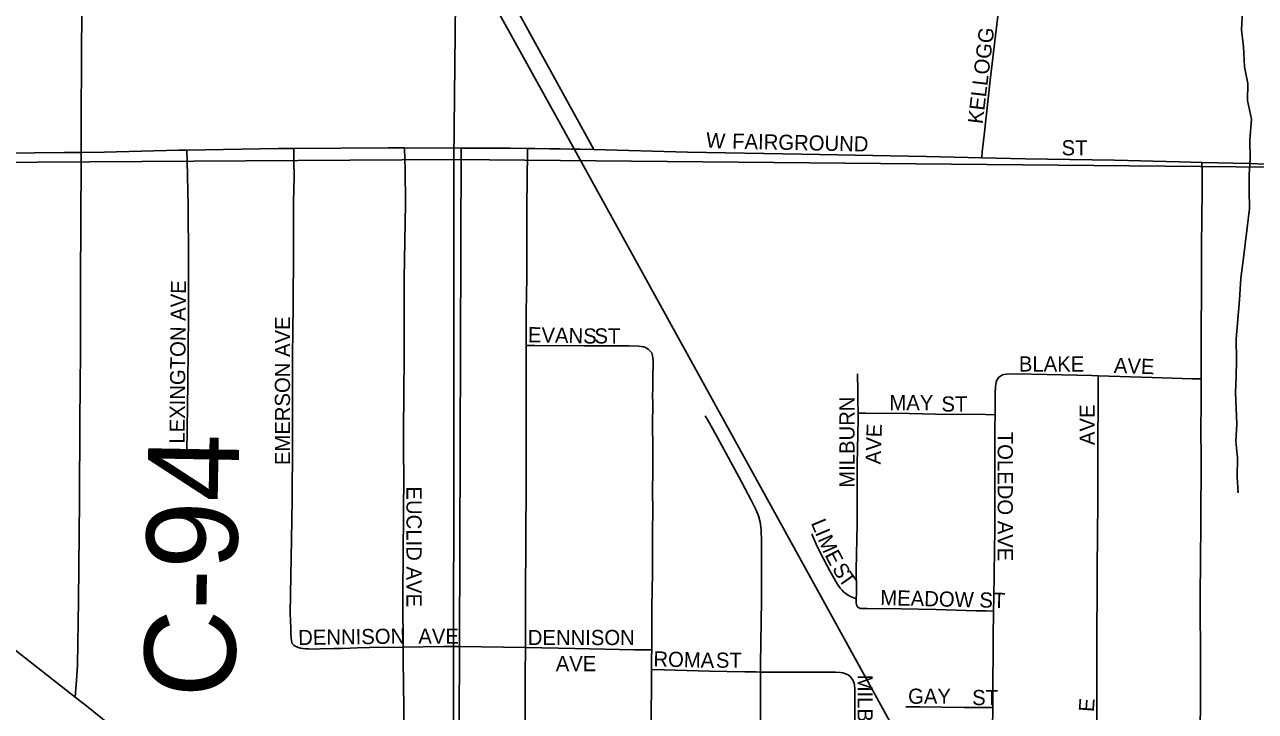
# Model space of a CAD drawing. Extents: x 1584893 to 1934202, y 663575 to 1091909.
# Drawn here: x 1786466 to 1790524, y 945999 to 948263 of the extents above; entities that cross this region are included whole.
import ezdxf

# ---------------------------------------------------------------- set-up
doc = ezdxf.new("R2010")
doc.units = 0
for name, color, linetype in [('GM_X_City_Street', 7, 'Continuous'), ('GM_X_City_Street_Text', 7, 'Continuous'), ('GM_X_Corporation', 7, 'Continuous'), ('GM_X_County_Road', 7, 'Continuous'), ('GM_X_County_Road_Text', 7, 'Continuous'), ('GM_X_Minor_River', 7, 'Continuous'), ('GM_X_Rail_Line', 7, 'Continuous'), ('GM_X_Section', 7, 'Continuous'), ('GM_X_State_Route', 7, 'Continuous'), ('GM_X_Township_Subdivision', 7, 'Continuous'), ('GM_X_Township_Subdivision_Text', 7, 'Continuous')]:
    doc.layers.add(name, color=color, linetype=linetype)

msp = doc.modelspace()

# ---------------------------------------------------------------- linework, layer by layer
at = {"layer": 'GM_X_City_Street'}
for points in [[(1789621.1, 947824.3), (1789623.2, 947844.1), (1789628.9, 947898.8), (1789648.8, 948079.7), (1789674.4, 948291.5)], [(1788119.7, 947205.2), (1788119.7, 947314.6), (1788121.2, 947429.3), (1788121.7, 947642.4), (1788122.3, 947773.6), (1788123.2, 947822.8), (1788123.9, 947855.2)], [(1788342.3, 947851), (1788651.7, 947843.1), (1789028.3, 947835.8), (1789437.6, 947828.2), (1789621.1, 947824.3)], [(1789621.1, 947824.3), (1789765, 947821.1), (1790059.6, 947815.7), (1790272.5, 947811), (1790347.4, 947809)], [(1790344.6, 947094.7), (1790344.6, 947271.2), (1790345.5, 947369.4), (1790345.9, 947533.2), (1790348, 947713.5), (1790347.6, 947784.3), (1790347.4, 947809)], [(1790347.4, 947809), (1790501.7, 947804.7), (1790559.1, 947802.8)], [(1788116.7, 946209.3), (1788116.7, 946217.2), (1788116.7, 946396.9), (1788118.4, 946544.5), (1788119, 946773.5), (1788119.7, 947167), (1788119.7, 947205.2)], [(1788119.7, 947205.2), (1788147.5, 947205), (1788311.2, 947203.9), (1788458.6, 947204.1), (1788491.2, 947202.5), (1788498.4, 947202), (1788507.2, 947200.4), (1788512.7, 947198.2), (1788516.2, 947196.1), (1788521.8, 947192.6), (1788528.6, 947186.7)], [(1788533.2, 946201.4), (1788534.1, 946242.1), (1788533.4, 946340.6), (1788536, 946455.6), (1788535.5, 946487.9), (1788535.4, 946504.2), (1788535.7, 946602.3), (1788536.4, 946651.3), (1788536, 946733.4), (1788536.6, 946782.6), (1788537.2, 946864.6), (1788535.6, 946946.4), (1788536.6, 947011.3), (1788536.2, 947043.9), (1788536.6, 947059.3), (1788536.8, 947075.2), (1788536.7, 947090.8), (1788537.5, 947155.9), (1788537.3, 947163.6), (1788536.1, 947172.3), (1788533.2, 947180.4), (1788528.6, 947186.7)], [(1789213.6, 946981.5), (1789213.1, 947023.3), (1789212.5, 947066), (1789212, 947101), (1789211.9, 947111.3)], [(1789671.1, 947091.3), (1789677.8, 947100.3), (1789683.2, 947104.5), (1789689.4, 947108.1), (1789695.7, 947109.6), (1789703.3, 947110.3), (1789736.2, 947111.7), (1789835.5, 947109.3), (1789984.5, 947105.8), (1790005, 947105.2)], [(1789995.8, 945159.5), (1789995.8, 945195.4), (1789995.8, 945385.1), (1789996.3, 945482.8), (1789997.2, 945677.2), (1789998, 945820.7), (1790000.3, 945980.3), (1790001.3, 946163.8), (1790001.9, 946488.6), (1790003.1, 946563.6), (1790004.1, 946705.9), (1790004.3, 946835.3), (1790004.9, 947065.2), (1790004.9, 947081.6), (1790005, 947105.2)], [(1790005, 947105.2), (1790183.1, 947100), (1790315.4, 947095.6), (1790344.6, 947094.7)], [(1790336.9, 945152.3), (1790337.4, 945195.9), (1790339.7, 945425.5), (1790340.1, 945605.5), (1790340.1, 945687.6), (1790338.9, 945721), (1790339.2, 945734.4), (1790339.5, 945781.5), (1790339.8, 945847.1), (1790342.5, 946010.9), (1790342.5, 946125.8), (1790341.8, 946404.4), (1790342.2, 946469.8), (1790344.9, 946814.2), (1790344.2, 946945.5), (1790344.6, 946994.5), (1790344.6, 947094.7)], [(1789665.2, 946977), (1789665.4, 947035.7), (1789666.1, 947055), (1789666.4, 947062.4), (1789667.2, 947068.6), (1789668, 947077.2), (1789669.2, 947083.1), (1789671.1, 947091.3)], [(1788892, 946128.3), (1788892.2, 946153), (1788894.8, 946365.5), (1788895.1, 946463.2), (1788894.9, 946560.7), (1788895.1, 946570.8), (1788894.5, 946583.8), (1788893.8, 946593.8), (1788892.6, 946607.5), (1788890.7, 946623), (1788885.7, 946643.5), (1788877.1, 946662.1), (1788867.9, 946681.8), (1788860.9, 946695.1), (1788851.2, 946713.5), (1788820.3, 946771.8), (1788758, 946887.2), (1788718.1, 946958.8), (1788709.9, 946973)], [(1789207.3, 946369.5), (1789207.6, 946376.7), (1789207.9, 946383.2), (1789208.4, 946400.6), (1789207.8, 946466.8), (1789211.1, 946615.5), (1789211, 946813.9), (1789213.9, 946962.5), (1789213.6, 946981.5)], [(1789213.6, 946981.5), (1789239.5, 946981.5), (1789272.3, 946981.4), (1789337.9, 946981.5), (1789469.1, 946979.1), (1789633.2, 946977.3), (1789665.2, 946977)], [(1789660.2, 946329.5), (1789660.9, 946373.3), (1789662.3, 946454.7), (1789664.1, 946600.8), (1789664.5, 946693.9), (1789665, 946937.4), (1789665.2, 946977)], [(1789207.3, 946369.5), (1789191.2, 946376), (1789178.6, 946382.8), (1789165.7, 946393.1), (1789160.8, 946398), (1789154.7, 946405.4), (1789145.1, 946418.8), (1789120.7, 946462), (1789090.2, 946520.8), (1789074.9, 946550.2), (1789068.3, 946565.3), (1789062.7, 946580.9), (1789062, 946583.6)], [(1789215.8, 946340.2), (1789211.6, 946343.5), (1789208.7, 946349.7), (1789207.7, 946356.5), (1789207.3, 946369.5)], [(1789215.8, 946340.2), (1789218.9, 946338.9), (1789221.6, 946338.3), (1789225, 946337.9), (1789228.7, 946338.1), (1789234.1, 946338.1), (1789243.2, 946338.2), (1789355.4, 946337.3), (1789470.9, 946335.1), (1789602.8, 946330.4), (1789635.7, 946329.9), (1789660.2, 946329.5)], [(1789657.9, 946011.8), (1789658.3, 946046.6), (1789658.9, 946242.8), (1789660.2, 946329.5)], [(1788116.7, 946209.3), (1787899.9, 946213.1)], [(1788112.7, 945197), (1788112.9, 945238.3), (1788113.4, 945402.2), (1788115.8, 945582.3), (1788115.4, 945664.2), (1788114, 945827.5), (1788114.5, 945876.3), (1788115.8, 945957.5), (1788116.3, 946119.6), (1788116.7, 946209.3)], [(1788116.7, 946209.3), (1788279.4, 946206.4), (1788475.9, 946201.9), (1788508.6, 946201.6), (1788533.2, 946201.4)], [(1788532.7, 946136.7), (1788532.6, 946176.4), (1788533.2, 946201.4)], [(1788527.7, 945188.6), (1788528.4, 945224), (1788529.2, 945256.8), (1788528.1, 945388.2), (1788530.9, 945568.8), (1788530.6, 945683.7), (1788532.1, 945880.8), (1788531.5, 945946.5), (1788532.8, 946127.1), (1788532.7, 946136.7)], [(1788532.7, 946136.7), (1788574.7, 946135.6), (1788724.1, 946131.5), (1788840.3, 946128.7), (1788876.9, 946128.7), (1788892, 946128.3)], [(1788886.3, 945181), (1788886.5, 945221.2), (1788888.9, 945646.2), (1788889.4, 945891.6), (1788891.4, 945973.4), (1788892.1, 946087.7), (1788892, 946128.3)], [(1788892, 946128.3), (1789039.5, 946128.4), (1789139, 946127.5), (1789155.6, 946126.5), (1789163.6, 946125.4), (1789171.8, 946122.7), (1789180.4, 946119)], [(1789199.8, 945543.2), (1789199.9, 945549.9), (1789201.6, 945664.2), (1789202.8, 945713.1), (1789201.9, 945748.6), (1789201.2, 945778.5), (1789203, 945942.5), (1789202.8, 946024.6), (1789202.6, 946073.9), (1789202.4, 946077.5), (1789202, 946081.5), (1789201.3, 946085.9), (1789200.2, 946090.1), (1789198.3, 946096.9), (1789196.8, 946101.1), (1789194.3, 946105), (1789191.1, 946109.8), (1789187.1, 946114), (1789180.4, 946119)], [(1789370.7, 946013.8), (1789418.1, 946013.9), (1789562.4, 946011.7), (1789625.9, 946011.8), (1789657.9, 946011.8)], [(1789863.6, 945162), (1789844.5, 945195), (1789819.9, 945237.6), (1789740.4, 945380.5), (1789677, 945495.1), (1789663, 945525.3), (1789657.8, 945541.4), (1789655.1, 945558), (1789653.7, 945591.2), (1789653.1, 945656.5), (1789653.5, 945721.4), (1789656, 945867.5), (1789657.9, 946011.8)]]:
    msp.add_lwpolyline(points, dxfattribs=at)
at = {"layer": 'GM_X_Corporation'}
msp.add_lwpolyline([(1787866.1, 943680.2), (1787892.4, 945033.6), (1787894.8, 945201.7), (1787899.9, 946213.1), (1787904.8, 947855.9), (1788123.9, 947855.1), (1788342.3, 947851), (1786892.8, 950488)], dxfattribs=at)
at = {"layer": 'GM_X_County_Road'}
for points in [[(1786651.8, 947841.9), (1786651.8, 947982.3), (1786652.7, 948122.4), (1786654.3, 948351.1), (1786653.5, 948531.5)], [(1786301.9, 947838), (1786596.2, 947841.1), (1786651.8, 947841.9)], [(1786632, 946045.6), (1786636.2, 946102.1), (1786639.7, 946151), (1786643.2, 946364.2), (1786646.5, 946692.7), (1786647.8, 946955.4), (1786650.1, 947185.3), (1786650.1, 947415.1), (1786651.8, 947813.8), (1786651.8, 947841.9)], [(1786651.8, 947841.9), (1786727.4, 947842.7), (1786973.6, 947849.1), (1787000.9, 947849.4)], [(1787000.9, 947849.4), (1787121.1, 947851.2), (1787301.6, 947854.6), (1787352.8, 947854.9)], [(1787352.8, 947854.9), (1787662.9, 947856.7), (1787717.9, 947856.5)], [(1787717.9, 947856.5), (1787904.8, 947855.9)], [(1787904.8, 947855.9), (1788066.3, 947855.7), (1788123.9, 947855.2)], [(1788123.9, 947855.2), (1788148.8, 947854.9), (1788231.3, 947853.6), (1788297.3, 947852), (1788342.3, 947851)]]:
    msp.add_lwpolyline(points, dxfattribs=at)
at = {"layer": 'GM_X_Minor_River'}
msp.add_lwpolyline([(1790480.6, 948308), (1790477.6, 948246), (1790484.7, 948189.8), (1790487.5, 948123.7), (1790498.6, 948069.4), (1790497.7, 948013.4), (1790510.6, 947951.2), (1790505.5, 947883.2), (1790506.5, 947821.1), (1790503.6, 947769.1), (1790502.8, 947717.1), (1790503.8, 947657), (1790496.7, 947593.1), (1790482.9, 947485.3), (1790476, 947427.3), (1790470.8, 947355.4), (1790460.7, 947227.4), (1790461.5, 947155.4), (1790460.6, 947103.3), (1790457.7, 947049.3), (1790462, 946945.2), (1790459.1, 946889.2), (1790464.2, 946835.1), (1790463.1, 946771), (1790466.3, 946720.9), (1790464.3, 946725)], dxfattribs=at)
at = {"layer": 'GM_X_Rail_Line'}
msp.add_lwpolyline([(1789400.6, 945815.7), (1789127.2, 946312.4), (1788279, 947851.2), (1787937.1, 948469), (1787819.8, 948676.5), (1787624.4, 949012.2), (1787505.6, 949248.9), (1787424.3, 949403.4), (1787265.8, 949688.4), (1785374.8, 953122.4), (1784266.3, 955133.8), (1784098.1, 955439.7), (1784015.4, 955585.7), (1783944.2, 955691.7), (1783794.4, 955967.2), (1783640.1, 956257.8), (1783519.3, 956485.2)], dxfattribs=at)
at = {"layer": 'GM_X_Section'}
for points in [[(1782828, 953093.9), (1787937.3, 953135.4), (1787881.1, 947818.8), (1782733.9, 947785.7)], [(1787937.3, 953135.4), (1793211.7, 953051.5), (1793155.7, 947768.8), (1787881.1, 947818.8)], [(1782733.9, 947785.7), (1787881.1, 947818.8), (1787878.9, 942509.8), (1782631.8, 942485.5)], [(1787881.1, 947818.8), (1793155.7, 947768.8), (1793145.7, 942483.9), (1787878.9, 942509.8)]]:
    msp.add_lwpolyline(points, close=True, dxfattribs=at)
at = {"layer": 'GM_X_State_Route'}
msp.add_lwpolyline([(1784411.4, 947809), (1784778, 947519.7), (1784956.6, 947377.5), (1785123.6, 947244.7), (1785149.2, 947224.2), (1785341.7, 947070.9), (1785637.5, 946836.6), (1785996.9, 946550.6), (1786138.3, 946438.4), (1786290.4, 946316.4), (1786407, 946222.8), (1786632, 946045.6), (1786664.7, 946019.9), (1787048.2, 945711.3), (1787418.9, 945413.2), (1787632.7, 945242.8), (1787680.6, 945204.5), (1787741.5, 945155.3), (1787772.6, 945130), (1787892.5, 945033.6)], dxfattribs=at)
at = {"layer": 'GM_X_Township_Subdivision'}
for points in [[(1787000, 946850.3), (1787001.4, 946931.9), (1787004.1, 947078.7), (1787005.9, 947307), (1787006.2, 947421.2), (1787005.7, 947486.4), (1787004.6, 947665.8), (1787001.6, 947812.5), (1787000.9, 947849.4)], [(1787347.3, 946222.5), (1787345.2, 946231.8), (1787344.1, 946240.4), (1787342.9, 946257), (1787342.8, 946272.6), (1787341.3, 946321.1), (1787342.1, 946385), (1787345.2, 946565.2), (1787347.2, 946696.7), (1787348.5, 946877.2), (1787348.3, 946973.5), (1787348.8, 947057.1), (1787349, 947172.1), (1787351, 947336.3), (1787351.7, 947516.8), (1787352.6, 947680.8), (1787353.6, 947718.6), (1787353.9, 947762.8), (1787353.3, 947812), (1787352.8, 947854.9)], [(1787713.8, 946210.9), (1787712.8, 946362.7), (1787713.9, 946542.8), (1787714.8, 946624.7), (1787714.8, 946640.9), (1787715.5, 946787.9), (1787715, 946837), (1787715, 946918.9), (1787715.4, 947049.9), (1787716.9, 947164.6), (1787716.7, 947426.7), (1787721, 947672.3), (1787719.9, 947786.9), (1787719, 947819.6), (1787717.9, 947856.5)], [(1787713.8, 946210.9), (1787602.6, 946209.4), (1787563, 946208), (1787539.5, 946207.4), (1787509.9, 946206.5), (1787485.1, 946205.8), (1787440.1, 946204.5), (1787423.6, 946203.9), (1787402.4, 946204.4), (1787391.3, 946205.1), (1787383.2, 946205.8), (1787375.2, 946207.3), (1787367.4, 946209.5), (1787362.7, 946211.7), (1787357.8, 946213.9), (1787353.7, 946217.1), (1787347.3, 946222.5)], [(1787899.9, 946213.1), (1787846.8, 946212.8), (1787713.8, 946210.9)], [(1787717.9, 945853.8), (1787714.1, 946166.2), (1787713.8, 946210.9)]]:
    msp.add_lwpolyline(points, dxfattribs=at)

# ---------------------------------------------------------------- texts
at = {"layer": 'GM_X_City_Street_Text'}
for s, rotation, p in [('KELLOGG', 83.0895, (1789624.4, 947933.8)), ('W', 355.6039, (1788710.4, 947858.5)), ('FAIRGROUND', 358.7392, (1788797.9, 947854.1)), ('ST', 0, (1789884.5, 947832.1)), ('EVANS', 358.7243, (1788124.7, 947216.1)), ('ST', 0, (1788344.5, 947211.7)), ('BLAKE', 0, (1789743.7, 947119.3)), ('AVE', 358.0264, (1790056.4, 947114.9)), ('MILBURN', 90, (1789201.9, 946735.9)), ('MAY', 0, (1789316.9, 946991.7)), ('ST', 0, (1789488.5, 946987.3)), ('AVE', 90, (1789993.9, 946876.7)), ('AVE', 88.0918, (1789287.8, 946812.6)), ('TOLEDO AVE', 270, (1789673.9, 946920.7)), ('L', 292.5421, (1789057.3, 946620.4)), ('I', 292.6003, (1789070.8, 946587.9)), ('M', 293.3806, (1789079.5, 946566.9)), ('E', 297.7847, (1789102.3, 946514.6)), ('S', 300.5795, (1789126.3, 946469.6)), ('T', 305.0375, (1789146.5, 946435.7)), ('MEADOW ST', 358.6182, (1789286.3, 946349.3)), ('DENNISON', 0, (1788124.5, 946217.3)), ('AVE', 0, (1788216.9, 946131.3)), ('ROMA', 358.6368, (1788538.3, 946146.9)), ('ST', 0, (1788744.9, 946142.5)), ('MILBURN AVE', 270, (1789211.9, 946119.9)), ('GAY', 0, (1789378.5, 946023.7)), ('ST', 0, (1789589.7, 946019.3)), ('E', 86.1168, (1789990.8, 945995.8))]:
    msp.add_text(s, height=50, rotation=rotation, dxfattribs=at).set_placement(p)
at = {"layer": 'GM_X_County_Road_Text'}
msp.add_text('C-94', height=300, rotation=88.9861, dxfattribs=at).set_placement((1787158.5, 946042.1))
at = {"layer": 'GM_X_Township_Subdivision_Text'}
for s, rotation, p in [('LEXINGTON AVE', 89.4819, (1786993.1, 946881.2)), ('EMERSON AVE', 90, (1787340.7, 946810.7)), ('EUCLID AVE', 270, (1787724.7, 946740.3)), ('DENNISON', 0.7965, (1787367.9, 946217.3)), ('AVE', 0, (1787763.7, 946221.7))]:
    msp.add_text(s, height=50, rotation=rotation, dxfattribs=at).set_placement(p)

doc.saveas('drawing.dxf')
